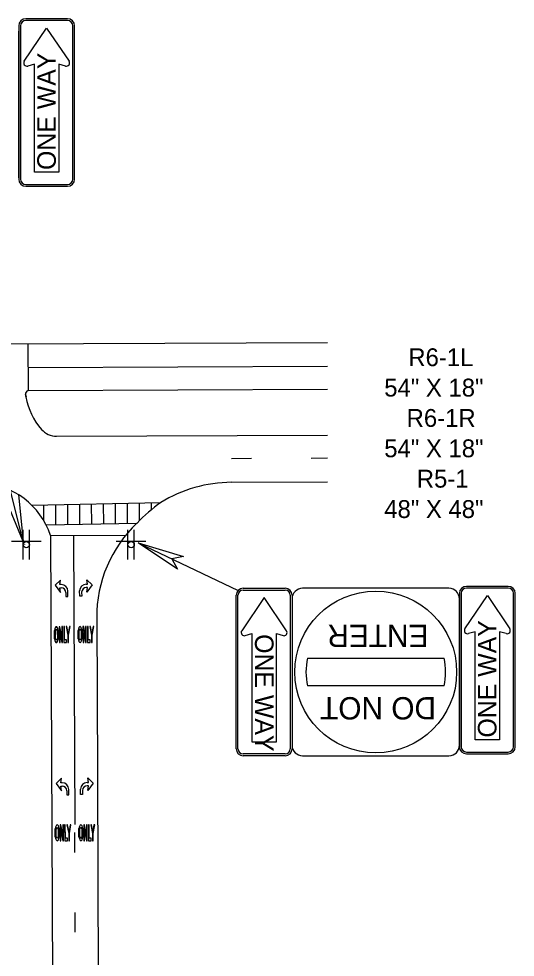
# Model space of a CAD drawing. Extents: x 582908 to 586039, y 1530940 to 1532988.
# Drawn here: x 585649 to 586038, y 1532013 to 1532748 of the extents above; entities that cross this region are included whole.
import ezdxf

# ---------------------------------------------------------------- set-up
doc = ezdxf.new("R2010")
doc.units = 0
for name, color, linetype in [('DirArrowsPavt', 7, 'Continuous'), ('LeaderLine_dp', 7, 'Continuous'), ('PavtMessage', 7, 'Continuous'), ('PMStripe12W', 7, 'Continuous'), ('PMStripe24W', 7, 'Continuous'), ('PMStripe6W', 7, 'Continuous'), ('PMStripe6W(10-30)', 7, 'Continuous'), ('PMStripe6Y', 7, 'Continuous'), ('PMStripe8W', 7, 'Continuous'), ('Scratch2_dp', 7, 'Continuous'), ('SignPanel', 7, 'Continuous'), ('SignSupport', 7, 'Continuous'), ('TextLabel', 7, 'Continuous'), ('TextShtNo', 7, 'Continuous')]:
    doc.layers.add(name, color=color, linetype=linetype)

# ---------------------------------------------------------------- blocks, each defined once
blk = doc.blocks.new('ArrTermPnt')
at = {"layer": 'LeaderLine_dp'}
for p, q in [((-0.1, 0), (-0.12, 0.02)), ((-0.12, 0.02), (0, 0)), ((0, 0), (-0.12, -0.02)), ((-0.12, -0.02), (-0.1, 0))]:
    blk.add_line(p, q, dxfattribs=at)

msp = doc.modelspace()

# ---------------------------------------------------------------- linework, layer by layer
at = {"layer": 'DirArrowsPavt'}
for p, q in [((585681.41, 1532308.37), (585677.26, 1532304.31)), ((585680.9, 1532304.85), (585681.41, 1532308.37)), ((585702.61, 1532305.09), (585702.07, 1532308.6)), ((585702.07, 1532308.6), (585706.26, 1532304.58)), ((585677.26, 1532304.31), (585681.45, 1532298.6)), ((585681.94, 1532304.85), (585680.9, 1532304.85)), ((585681.45, 1532298.6), (585680.91, 1532302.25)), ((585680.91, 1532302.25), (585681.96, 1532302.25)), ((585687.19, 1532295.5), (585687.18, 1532299.67)), ((585696.4, 1532295.69), (585696.38, 1532299.85)), ((585701.57, 1532305.08), (585702.61, 1532305.09)), ((585702.62, 1532302.48), (585701.58, 1532302.48)), ((585706.26, 1532304.58), (585702.12, 1532298.84)), ((585702.12, 1532298.84), (585702.62, 1532302.48)), ((585685.62, 1532298.62), (585685.63, 1532295.5)), ((585685.63, 1532295.5), (585687.19, 1532295.5)), ((585697.96, 1532295.69), (585696.4, 1532295.69)), ((585697.95, 1532298.82), (585697.96, 1532295.69)), ((585682.1, 1532153.01), (585677.95, 1532148.95)), ((585681.59, 1532149.49), (585682.1, 1532153.01)), ((585703.3, 1532149.73), (585702.76, 1532153.24)), ((585702.76, 1532153.24), (585706.95, 1532149.22)), ((585677.95, 1532148.95), (585682.14, 1532143.24)), ((585682.63, 1532149.49), (585681.59, 1532149.49)), ((585681.6, 1532146.88), (585682.64, 1532146.89)), ((585682.14, 1532143.24), (585681.6, 1532146.88)), ((585702.26, 1532149.72), (585703.3, 1532149.73)), ((585703.31, 1532147.12), (585702.27, 1532147.12)), ((585706.95, 1532149.22), (585702.81, 1532143.47)), ((585702.81, 1532143.47), (585703.31, 1532147.12)), ((585686.31, 1532143.26), (585686.32, 1532140.13)), ((585686.32, 1532140.13), (585687.88, 1532140.14)), ((585687.88, 1532140.14), (585687.86, 1532144.31)), ((585697.09, 1532140.32), (585697.07, 1532144.49)), ((585698.65, 1532140.33), (585697.09, 1532140.32)), ((585698.64, 1532143.45), (585698.65, 1532140.33))]:
    msp.add_line(p, q, dxfattribs=at)
for centre, radius, start, end in [((585681.97, 1532299.65), 5.21, 0.25044, 90.25044), ((585681.97, 1532298.6), 3.65, 0.25044, 90.25044), ((585701.59, 1532299.87), 5.21, 90.25044, 180.25044), ((585701.6, 1532298.83), 3.65, 90.25044, 180.25044), ((585682.66, 1532144.28), 5.21, 0.25044, 90.25044), ((585682.66, 1532143.24), 3.65, 0.25044, 90.25044), ((585702.28, 1532144.51), 5.21, 90.25044, 180.25044), ((585702.28, 1532143.47), 3.65, 90.25044, 180.25044)]:
    msp.add_arc(centre, radius, start, end, dxfattribs=at)
at = {"layer": 'LeaderLine_dp'}
for p, q in [((585652.03, 1532338.6), (585583, 1532615.55)), ((585652.03, 1532338.6), (585637.86, 1532372.76)), ((585648.51, 1532375.42), (585652.03, 1532338.6)), ((585742.33, 1532337.53), (585820.77, 1532300.32)), ((585742.33, 1532337.53), (585777.73, 1532326.81)), ((585773.02, 1532316.9), (585742.33, 1532337.53)), ((585777.73, 1532326.81), (585768.76, 1532324.99)), ((585768.76, 1532324.99), (585773.02, 1532316.9))]:
    msp.add_line(p, q, dxfattribs=at)
at = {"layer": 'PavtMessage'}
for p, q in [((585680.41, 1532271.84), (585680.47, 1532259.34)), ((585680.94, 1532271.84), (585680.41, 1532271.84)), ((585682.4, 1532263.88), (585680.94, 1532271.84)), ((585682.89, 1532271.85), (585682.37, 1532271.85)), ((585682.37, 1532271.85), (585682.4, 1532263.88)), ((585682.94, 1532259.35), (585682.89, 1532271.85)), ((585684.45, 1532271.86), (585683.93, 1532271.85)), ((585683.93, 1532271.85), (585683.99, 1532259.35)), ((585684.5, 1532261.44), (585684.45, 1532271.86)), ((585686.28, 1532271.86), (585685.75, 1532271.86)), ((585685.75, 1532271.86), (585687.09, 1532265.1)), ((585687.34, 1532266.5), (585686.28, 1532271.86)), ((585688.35, 1532271.87), (585687.34, 1532266.5)), ((585687.61, 1532265.1), (585688.88, 1532271.87)), ((585688.88, 1532271.87), (585688.35, 1532271.87)), ((585698.99, 1532271.92), (585699.05, 1532259.42)), ((585699.52, 1532271.92), (585698.99, 1532271.92)), ((585700.98, 1532263.96), (585699.52, 1532271.92)), ((585701.47, 1532271.93), (585700.95, 1532271.93)), ((585700.95, 1532271.93), (585700.98, 1532263.96)), ((585701.52, 1532259.43), (585701.47, 1532271.93)), ((585702.51, 1532271.94), (585702.57, 1532259.44)), ((585703.03, 1532271.94), (585702.51, 1532271.94)), ((585703.08, 1532261.52), (585703.03, 1532271.94)), ((585704.86, 1532271.95), (585704.33, 1532271.94)), ((585704.33, 1532271.94), (585705.67, 1532265.18)), ((585705.92, 1532266.58), (585704.86, 1532271.95)), ((585706.93, 1532271.95), (585705.92, 1532266.58)), ((585706.19, 1532265.18), (585707.46, 1532271.96)), ((585707.46, 1532271.96), (585706.93, 1532271.95)), ((585676.55, 1532262.35), (585676.52, 1532268.79)), ((585677.05, 1532268.07), (585677.07, 1532263.07)), ((585679.15, 1532263.08), (585679.13, 1532268.08)), ((585679.65, 1532268.8), (585679.68, 1532262.36)), ((585680.99, 1532259.34), (585680.96, 1532267.15)), ((585680.96, 1532267.15), (585682.42, 1532259.35)), ((585687.09, 1532265.1), (585687.11, 1532259.37)), ((585687.63, 1532259.37), (585687.61, 1532265.1)), ((585695.13, 1532262.43), (585695.1, 1532268.87)), ((585695.63, 1532268.15), (585695.65, 1532263.15)), ((585697.73, 1532263.16), (585697.71, 1532268.16)), ((585698.23, 1532268.89), (585698.26, 1532262.45)), ((585699.57, 1532259.42), (585699.54, 1532267.23)), ((585699.54, 1532267.23), (585701, 1532259.43)), ((585705.67, 1532265.18), (585705.69, 1532259.45)), ((585706.21, 1532259.45), (585706.19, 1532265.18)), ((585680.47, 1532259.34), (585680.99, 1532259.34)), ((585682.42, 1532259.35), (585682.94, 1532259.35)), ((585683.99, 1532259.35), (585686.07, 1532259.36)), ((585686.06, 1532261.45), (585684.5, 1532261.44)), ((585686.07, 1532259.36), (585686.06, 1532261.45)), ((585687.11, 1532259.37), (585687.63, 1532259.37)), ((585699.05, 1532259.42), (585699.57, 1532259.42)), ((585701, 1532259.43), (585701.52, 1532259.43)), ((585702.57, 1532259.44), (585704.65, 1532259.44)), ((585704.64, 1532261.53), (585703.08, 1532261.52)), ((585704.65, 1532259.44), (585704.64, 1532261.53)), ((585705.69, 1532259.45), (585706.21, 1532259.45)), ((585681.1, 1532116.48), (585681.16, 1532103.98)), ((585681.62, 1532116.48), (585681.1, 1532116.48)), ((585683.09, 1532108.52), (585681.62, 1532116.48)), ((585683.58, 1532116.49), (585683.06, 1532116.48)), ((585683.06, 1532116.48), (585683.09, 1532108.52)), ((585683.63, 1532103.99), (585683.58, 1532116.49)), ((585684.62, 1532116.49), (585684.67, 1532103.99)), ((585685.14, 1532116.49), (585684.62, 1532116.49)), ((585685.19, 1532106.08), (585685.14, 1532116.49)), ((585686.97, 1532116.5), (585686.44, 1532116.5)), ((585686.44, 1532116.5), (585687.77, 1532109.73)), ((585688.03, 1532111.14), (585686.97, 1532116.5)), ((585689.04, 1532116.51), (585688.03, 1532111.14)), ((585688.29, 1532109.74), (585689.57, 1532116.51)), ((585689.57, 1532116.51), (585689.04, 1532116.51)), ((585699.68, 1532116.56), (585699.74, 1532104.06)), ((585700.2, 1532116.56), (585699.68, 1532116.56)), ((585701.67, 1532108.6), (585700.2, 1532116.56)), ((585702.16, 1532116.57), (585701.64, 1532116.57)), ((585701.64, 1532116.57), (585701.67, 1532108.6)), ((585702.21, 1532104.07), (585702.16, 1532116.57)), ((585703.72, 1532116.58), (585703.2, 1532116.57)), ((585703.2, 1532116.57), (585703.25, 1532104.07)), ((585703.77, 1532106.16), (585703.72, 1532116.58)), ((585705.55, 1532116.58), (585705.02, 1532116.58)), ((585705.02, 1532116.58), (585706.35, 1532109.82)), ((585706.61, 1532111.22), (585705.55, 1532116.58)), ((585707.62, 1532116.59), (585706.61, 1532111.22)), ((585706.87, 1532109.82), (585708.15, 1532116.59)), ((585708.15, 1532116.59), (585707.62, 1532116.59)), ((585677.24, 1532106.99), (585677.21, 1532113.43)), ((585677.73, 1532112.71), (585677.76, 1532107.71)), ((585679.84, 1532107.72), (585679.82, 1532112.72)), ((585680.34, 1532113.44), (585680.36, 1532107)), ((585681.68, 1532103.98), (585681.65, 1532111.79)), ((585681.65, 1532111.79), (585683.11, 1532103.98)), ((585687.77, 1532109.73), (585687.8, 1532104)), ((585688.32, 1532104.01), (585688.29, 1532109.74)), ((585695.82, 1532107.07), (585695.79, 1532113.51)), ((585696.31, 1532112.79), (585696.34, 1532107.79)), ((585698.42, 1532107.8), (585698.4, 1532112.8)), ((585698.92, 1532113.52), (585698.94, 1532107.08)), ((585700.26, 1532104.06), (585700.22, 1532111.87)), ((585700.22, 1532111.87), (585701.69, 1532104.07)), ((585706.35, 1532109.82), (585706.38, 1532104.09)), ((585706.9, 1532104.09), (585706.87, 1532109.82)), ((585681.16, 1532103.98), (585681.68, 1532103.98)), ((585683.11, 1532103.98), (585683.63, 1532103.99)), ((585684.67, 1532103.99), (585686.76, 1532104)), ((585686.75, 1532106.08), (585685.19, 1532106.08)), ((585686.76, 1532104), (585686.75, 1532106.08)), ((585687.8, 1532104), (585688.32, 1532104.01)), ((585699.74, 1532104.06), (585700.26, 1532104.06)), ((585701.69, 1532104.07), (585702.21, 1532104.07)), ((585703.25, 1532104.07), (585705.34, 1532104.08)), ((585705.33, 1532106.17), (585703.77, 1532106.16)), ((585705.34, 1532104.08), (585705.33, 1532106.17)), ((585706.38, 1532104.09), (585706.9, 1532104.09))]:
    msp.add_line(p, q, dxfattribs=at)
for centre, major_axis, ratio, start_param, end_param in [((585678.1, 1532265.58), (-0.03, 6.25), 0.291667, 5.253489, 7.312882), ((585678.1, 1532265.58), (-0.02, 4.17), 0.3125, 5.35589, 7.210481), ((585696.68, 1532265.66), (-0.03, 6.25), 0.291667, 5.253489, 7.312882), ((585696.68, 1532265.66), (-0.02, 4.17), 0.3125, 5.35589, 7.210481), ((585678.1, 1532265.58), (-0.02, 4.17), 0.3125, 2.214297, 4.068888), ((585696.68, 1532265.66), (-0.03, 6.25), 0.291667, 2.111896, 4.171289), ((585696.68, 1532265.66), (-0.02, 4.17), 0.3125, 2.214297, 4.068888), ((585678.1, 1532265.58), (-0.03, 6.25), 0.291667, 2.111896, 4.171289), ((585678.79, 1532110.21), (-0.03, 6.25), 0.291667, 5.253489, 7.312882), ((585697.37, 1532110.3), (-0.03, 6.25), 0.291667, 5.253489, 7.312882), ((585678.79, 1532110.21), (-0.02, 4.17), 0.3125, 5.35589, 7.210481), ((585697.37, 1532110.3), (-0.02, 4.17), 0.3125, 5.35589, 7.210481), ((585678.79, 1532110.21), (-0.03, 6.25), 0.291667, 2.111896, 4.171289), ((585678.79, 1532110.21), (-0.02, 4.17), 0.3125, 2.214297, 4.068888), ((585697.37, 1532110.3), (-0.03, 6.25), 0.291667, 2.111896, 4.171289), ((585697.37, 1532110.3), (-0.02, 4.17), 0.3125, 2.214297, 4.068888)]:
    msp.add_ellipse(centre, major_axis=major_axis, ratio=ratio, start_param=start_param, end_param=end_param, dxfattribs=at)
at = {"layer": 'PMStripe12W'}
for p, q in [((585658.77, 1532367.1), (585759.94, 1532369.04)), ((585670.03, 1532351.68), (585741.4, 1532353.06))]:
    msp.add_line(p, q, dxfattribs=at)
at = {"layer": 'PMStripe24W'}
for p, q in [((585655.85, 1532493.67), (585656.01, 1532456.95)), ((585658.91, 1532366.96), (585658.91, 1532367.1)), ((585668.34, 1532354.79), (585668.28, 1532367.28)), ((585677.72, 1532351.83), (585677.66, 1532367.46)), ((585687.1, 1532352.01), (585687.03, 1532367.64)), ((585696.47, 1532352.19), (585696.4, 1532367.82)), ((585705.85, 1532352.37), (585705.78, 1532368)), ((585715.22, 1532352.56), (585715.15, 1532368.18)), ((585724.6, 1532352.74), (585724.53, 1532368.36)), ((585733.97, 1532352.92), (585733.9, 1532368.54)), ((585743.34, 1532355.06), (585743.28, 1532368.72)), ((585752.67, 1532363.56), (585752.65, 1532368.9)), ((585673.51, 1532343.28), (585732.57, 1532343.54))]:
    msp.add_line(p, q, dxfattribs=at)
at = {"layer": 'PMStripe6W'}
for p, q in [((585655.93, 1532474.92), (585890.69, 1532475.96)), ((585691.48, 1532343.36), (585692.48, 1532116.8)), ((585710.27, 1532156.53), (585710.98, 1531996.22))]:
    msp.add_line(p, q, dxfattribs=at)
at = {"layer": 'PMStripe6W(10-30)'}
for p, q in [((585815.38, 1532403.75), (585831.01, 1532403.82)), ((585877.88, 1532404.03), (585890.69, 1532404.08)), ((585692.58, 1532094.76), (585692.51, 1532110.39)), ((585692.86, 1532032.26), (585692.79, 1532047.89))]:
    msp.add_line(p, q, dxfattribs=at)
at = {"layer": 'PMStripe6Y'}
for p, q in [((585656.01, 1532456.95), (585890.69, 1532457.99)), ((585678.32, 1532421.11), (585890.69, 1532422.05)), ((585673.51, 1532343.28), (585675.05, 1531996.07))]:
    msp.add_line(p, q, dxfattribs=at)
for centre, radius, start, end in [((585656.83, 1532454.2), 2.87, 106.48711, 189.65536), ((585962.08, 1532506.13), 312.5, 189.65536, 189.98167), ((584884.32, 1532319.8), 781.25, 9.75502, 9.86944), ((585706.3, 1532461.12), 52.8, 189.98167, 220.99275), ((585678.25, 1532436.73), 15.62, 220.99275, 270.25398)]:
    msp.add_arc(centre, radius, start, end, dxfattribs=at)
at = {"layer": 'PMStripe8W'}
for p, q in [((585815.47, 1532385), (585890.69, 1532385.33)), ((585709.73, 1532278.92), (585710.27, 1532156.53))]:
    msp.add_line(p, q, dxfattribs=at)
msp.add_lwpolyline([(585443.93, 1532492.73), (585890.69, 1532494.71)], dxfattribs=at)
for centre, radius, start, end in [((585815.94, 1532278.75), 106.25, 90.25398, 121.80699), ((585811.29, 1532279.37), 101.56, 133.5482, 180.25398)]:
    msp.add_arc(centre, radius, start, end, dxfattribs=at)
at = {"layer": 'Scratch2_dp'}
msp.add_line((585655.85, 1532493.67), (585656.01, 1532456.95), dxfattribs=at)
at = {"layer": 'SignPanel'}
for p, q in [((585686.91, 1532748.33), (585654.1, 1532748.33)), ((585648.63, 1532742.86), (585648.63, 1532622.55)), ((585650, 1532742.86), (585650, 1532622.55)), ((585652.93, 1532715.1), (585670.5, 1532741.04)), ((585686.91, 1532746.96), (585654.1, 1532746.96)), ((585670.5, 1532741.04), (585688.07, 1532715.1)), ((585691.01, 1532622.55), (585691.01, 1532742.86)), ((585692.38, 1532622.55), (585692.38, 1532742.86)), ((585648.63, 1532623.75), (585648.63, 1532738.59)), ((585660.93, 1532712.78), (585655.7, 1532711.29)), ((585660.93, 1532628.02), (585660.93, 1532712.78)), ((585685.31, 1532711.29), (585680.07, 1532712.78)), ((585680.07, 1532712.78), (585680.07, 1532628.02)), ((585680.07, 1532628.02), (585660.93, 1532628.02)), ((585654.1, 1532618.45), (585686.91, 1532618.45)), ((585654.1, 1532617.08), (585686.91, 1532617.08)), ((585824.63, 1532301.92), (585857.45, 1532301.92)), ((585824.63, 1532300.55), (585857.45, 1532300.55)), ((585985.96, 1532301.92), (585871.12, 1532301.92)), ((586032.45, 1532303.45), (585999.63, 1532303.45)), ((586032.45, 1532302.09), (585999.63, 1532302.09)), ((585819.16, 1532176.14), (585819.16, 1532296.45)), ((585820.53, 1532176.14), (585820.53, 1532296.45)), ((585841.04, 1532294.63), (585823.47, 1532268.69)), ((585858.61, 1532268.69), (585841.04, 1532294.63)), ((585861.55, 1532296.45), (585861.55, 1532176.14)), ((585862.91, 1532296.45), (585862.91, 1532176.14)), ((585862.91, 1532293.71), (585862.91, 1532178.87)), ((585994.16, 1532297.98), (585994.16, 1532177.67)), ((585994.16, 1532178.87), (585994.16, 1532293.71)), ((585995.53, 1532297.98), (585995.53, 1532177.67)), ((585998.47, 1532270.22), (586016.04, 1532296.16)), ((586016.04, 1532296.16), (586033.61, 1532270.22)), ((586036.55, 1532177.67), (586036.55, 1532297.98)), ((586037.91, 1532177.67), (586037.91, 1532297.98)), ((585826.23, 1532264.87), (585831.47, 1532266.37)), ((585831.47, 1532266.37), (585831.47, 1532181.61)), ((585850.61, 1532266.37), (585855.85, 1532264.87)), ((585850.61, 1532181.61), (585850.61, 1532266.37)), ((586006.47, 1532267.9), (586001.23, 1532266.41)), ((586006.47, 1532183.14), (586006.47, 1532267.9)), ((586030.85, 1532266.41), (586025.61, 1532267.9)), ((586025.61, 1532267.9), (586025.61, 1532183.14)), ((585874.96, 1532247.23), (585982.12, 1532247.23)), ((585982.12, 1532225.36), (585874.96, 1532225.36)), ((585831.47, 1532181.61), (585850.61, 1532181.61)), ((586025.61, 1532183.14), (586006.47, 1532183.14)), ((585857.45, 1532172.04), (585824.63, 1532172.04)), ((585857.45, 1532170.67), (585824.63, 1532170.67)), ((585871.12, 1532170.67), (585985.96, 1532170.67)), ((585999.63, 1532173.57), (586032.45, 1532173.57)), ((585999.63, 1532172.2), (586032.45, 1532172.2))]:
    msp.add_line(p, q, dxfattribs=at)
msp.add_circle((585928.54, 1532236.29), 63.44, dxfattribs=at)
for centre, radius, start, end in [((585654.1, 1532742.86), 5.47, 90, 180), ((585686.91, 1532742.86), 5.47, 360, 90), ((585654.1, 1532742.86), 4.1, 90, 180), ((585686.91, 1532742.86), 4.1, 360, 90), ((585655.01, 1532713.7), 2.51, 145.88703, 285.93889), ((585686, 1532713.7), 2.51, 254.04541, 34.13318), ((585654.1, 1532622.55), 5.47, 180, 270), ((585654.1, 1532622.55), 4.1, 180, 270), ((585686.91, 1532622.55), 5.47, 270, 360), ((585686.91, 1532622.55), 4.1, 270, 360), ((585824.63, 1532296.45), 5.47, 90, 180), ((585824.63, 1532296.45), 4.1, 90, 180), ((585857.45, 1532296.45), 5.47, 360, 90), ((585857.45, 1532296.45), 4.1, 360, 90), ((585871.12, 1532293.71), 8.2, 90, 180), ((585985.96, 1532293.71), 8.2, 360, 90), ((585999.63, 1532297.98), 5.47, 90, 180), ((585999.63, 1532297.98), 4.1, 90, 180), ((586032.45, 1532297.98), 5.47, 360, 90), ((586032.45, 1532297.98), 4.1, 360, 90), ((586000.54, 1532268.82), 2.51, 145.88703, 285.93889), ((586031.53, 1532268.82), 2.51, 254.04541, 34.13318), ((585825.55, 1532267.28), 2.51, 145.86682, 285.95459), ((585856.53, 1532267.28), 2.51, 254.06111, 34.11297), ((585928.54, 1532236.29), 54.69, 168.46307, 191.53692), ((585928.54, 1532236.29), 54.69, 348.46307, 11.53692), ((585824.63, 1532176.14), 5.47, 180, 270), ((585824.63, 1532176.14), 4.1, 180, 270), ((585857.45, 1532176.14), 5.47, 270, 360), ((585857.45, 1532176.14), 4.1, 270, 360), ((585871.12, 1532178.87), 8.2, 180, 270), ((585985.96, 1532178.87), 8.2, 270, 360), ((585999.63, 1532177.67), 5.47, 180, 270), ((585999.63, 1532177.67), 4.1, 180, 270), ((586032.45, 1532177.67), 5.47, 270, 360), ((586032.45, 1532177.67), 4.1, 270, 360)]:
    msp.add_arc(centre, radius, start, end, dxfattribs=at)
at = {"layer": 'SignSupport'}
for p, q in [((585652.03, 1532324.47), (585652.03, 1532347.74)), ((585657.02, 1532324.47), (585657.02, 1532347.74)), ((585734.25, 1532324.47), (585734.25, 1532347.74)), ((585739.24, 1532324.47), (585739.24, 1532347.74)), ((585666.16, 1532338.6), (585642.89, 1532338.6)), ((585748.38, 1532338.6), (585725.11, 1532338.6))]:
    msp.add_line(p, q, dxfattribs=at)
for centre in [(585654.52, 1532336.11), (585736.75, 1532336.11)]:
    msp.add_circle(centre, 2.49, dxfattribs=at)
at = {"layer": 'TextShtNo'}
for centre, radius, start, end in [((585617.15, 1532324.88), 59.29, 18.08613, 87.94747), ((585828.12, 1532271.22), 119.24, 124.87666, 136.65942)]:
    msp.add_arc(centre, radius, start, end, dxfattribs=at)

# ---------------------------------------------------------------- block references
at = {"layer": 'TextLabel', "xscale": 2.041666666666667, "yscale": 1.9442318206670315, "rotation": -93.55208009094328}
msp.add_blockref('ArrTermPnt', (585653.1, 1532336.11), dxfattribs=at)

# ---------------------------------------------------------------- texts
at = {"layer": 'SignPanel'}
for s, height, rotation, p in [('ONE WAY', 14.567, 90, (585677.68, 1532629.81)), ('ENTER', 17.482, 180, (585969.83, 1532273.31)), ('ONE WAY', 14.567, 90, (586023.21, 1532184.93)), ('ONE WAY', 14.567, 270, (585833.86, 1532265.96)), ('DO NOT', 17.482, 180, (585975.79, 1532216.61))]:
    msp.add_text(s, height=height, rotation=rotation, dxfattribs=at).set_placement(p)
at = {"layer": 'TextLabel'}
for s, p in [('R6-1L', (585954.09, 1532476.03)), ('54" X 18"', (585935.21, 1532452.23)), ('R6-1R', (585952.76, 1532428.43)), ('54" X 18"', (585935.21, 1532404.63)), ('R5-1', (585960.72, 1532380.83)), ('48" X 48"', (585935.21, 1532357.03))]:
    msp.add_text(s, height=14, rotation=360, dxfattribs=at).set_placement(p)

doc.saveas('drawing.dxf')
